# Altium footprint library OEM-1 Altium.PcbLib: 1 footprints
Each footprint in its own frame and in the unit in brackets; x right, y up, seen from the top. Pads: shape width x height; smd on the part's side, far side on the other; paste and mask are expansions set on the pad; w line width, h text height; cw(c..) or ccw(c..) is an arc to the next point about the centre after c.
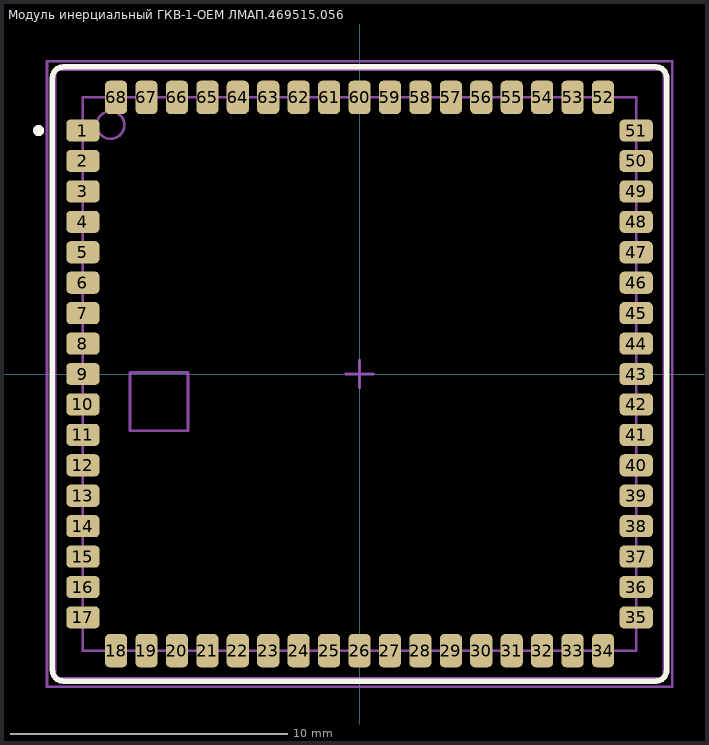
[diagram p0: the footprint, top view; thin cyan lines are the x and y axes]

## Модуль инерциальный ГКВ-1-OEM ЛМАП.469515.056 [mm]
height 4.5
pads (68):
  rrect40% 1.2x0.8 smd: 1(-10,8.8) 2(-10,7.7) 3(-10,6.6) 4(-10,5.5) 5(-10,4.4) 6(-10,3.3) 7(-10,2.2) 8(-10,1.1) 9(-10,0) 10(-10,-1.1) 11(-10,-2.2) 12(-10,-3.3) 13(-10,-4.4) 14(-10,-5.5) 15(-10,-6.6) 16(-10,-7.7) 17(-10,-8.8) 35(10,-8.8) 36(10,-7.7) 37(10,-6.6) 38(10,-5.5) 39(10,-4.4) 40(10,-3.3) 41(10,-2.2) 42(10,-1.1) 43(10,0) 44(10,1.1) 45(10,2.2) 46(10,3.3) 47(10,4.4) 48(10,5.5) 49(10,6.6) 50(10,7.7) 51(10,8.8)
  rrect40% 0.8x1.2 smd: 18(-8.8,-10) 19(-7.7,-10) 20(-6.6,-10) 21(-5.5,-10) 22(-4.4,-10) 23(-3.3,-10) 24(-2.2,-10) 25(-1.1,-10) 26(0,-10) 27(1.1,-10) 28(2.2,-10) 29(3.3,-10) 30(4.4,-10) 31(5.5,-10) 32(6.6,-10) 33(7.7,-10) 34(8.8,-10) 52(8.8,10) 53(7.7,10) 54(6.6,10) 55(5.5,10) 56(4.4,10) 57(3.3,10) 58(2.2,10) 59(1.1,10) 60(0,10) 61(-1.1,10) 62(-2.2,10) 63(-3.3,10) 64(-4.4,10) 65(-5.5,10) 66(-6.6,10) 67(-7.7,10) 68(-8.8,10)
Top Overlay:
  circle w0.2: c-11.6,8.8 r0.1
  lines w0.2: -11.1,-10.7 ccw(c-10.7,-10.7) -10.7,-11.1 10.7,-11.1 ccw(c10.7,-10.7) 11.1,-10.7 11.1,10.7 ccw(c10.7,10.7) 10.7,11.1 -10.7,11.1 ccw(c-10.7,10.7) -11.1,10.7 -11.1,-10.7
Mechanical 1:
  lines w0.1: -11,-11 11,-11 11,11 -11,11 -11,-11 ; -8.3,-2.05 -6.2,-2.05 -6.2,0.05 -8.3,0.05 -8.3,-2.05
Mechanical 13:
  circle w0.1: c-9,9 r0.5
  lines w0.1: -11,-11 11,-11 11,11 -11,11 -11,-11 ; -10,-10 10,-10 10,10 -10,10 -10,-10
  text ".Designator" at -1.428,-0.2 h1
Mechanical 15:
  lines w0.1: -0.5,0 0.5,0 ; 0,-0.5 0,0.5 ; -11.3,-11.3 11.3,-11.3 11.3,11.3 -11.3,11.3 -11.3,-11.3
3D body "ЛМАП.469515.056 Модуль инерциальный ГКВ-1-OEM.step": height 4.81, standoff -0.01, extent -11,-11 11,11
